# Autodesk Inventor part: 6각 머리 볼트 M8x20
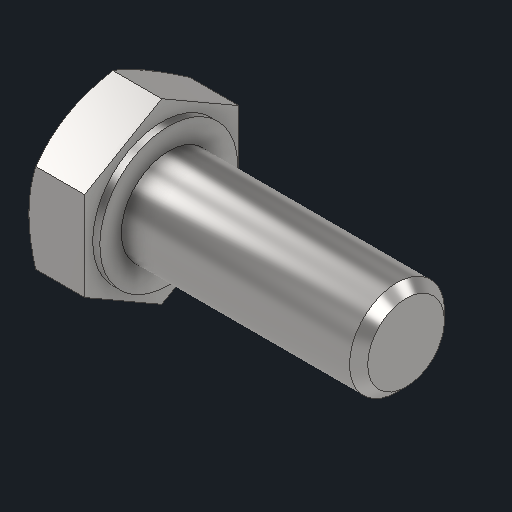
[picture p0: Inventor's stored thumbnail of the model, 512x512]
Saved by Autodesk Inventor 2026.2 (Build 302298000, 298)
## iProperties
Created: 2025-11
Part Number: 6각 머리 볼트 M8x20
Material: 강철, 연강
Description: 6각 머리 볼트 및 6각 머리 나사
Document SubType Name: Modeling
Designer: PC2-07
Density: 7.85 g/cm^3
Appearance: 기본값
Author: jhkim
Sending System: Autodesk Inventor 2026
Preprocessor: ST-DEVELOPER v20.1
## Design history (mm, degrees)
feature "Solid1"
node "솔리드1"
